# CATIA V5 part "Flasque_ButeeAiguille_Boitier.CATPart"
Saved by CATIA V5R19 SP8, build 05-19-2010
Part number: Flasque_ButéeAiguilles
Nomenclature: 70_f
Bounding box of the stored display mesh (mm): x -12.5 to 12.5, y -12.5 to 12.5, z 0 to 1
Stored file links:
  C:\Users\rphgr\Desktop\0_Tapis_TC520B_vitesse\Flasque_ButeeAiguille_Boitier.CATPart
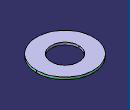
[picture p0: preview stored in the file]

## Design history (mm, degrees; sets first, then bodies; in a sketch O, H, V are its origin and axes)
Body1 (main body)
  AxisSystem1: origin (0, 0, 0), X (1, 0, 0), Y (0, 1, 0), Z (0, 0, 1)
  Sketch1 on XY plane of AxisSystem1, origin (0, 0, 0), H (1, 0, 0), V (0, 1, 0)
    circle A1 centre (0, 0) radius 6.1
    circle A2 centre (0, 0) radius 12.5
    radius A1 = 6.1
    radius A2 = 12.5
  Pad1: profile Sketch1, direction (0, 0, 1), length 1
